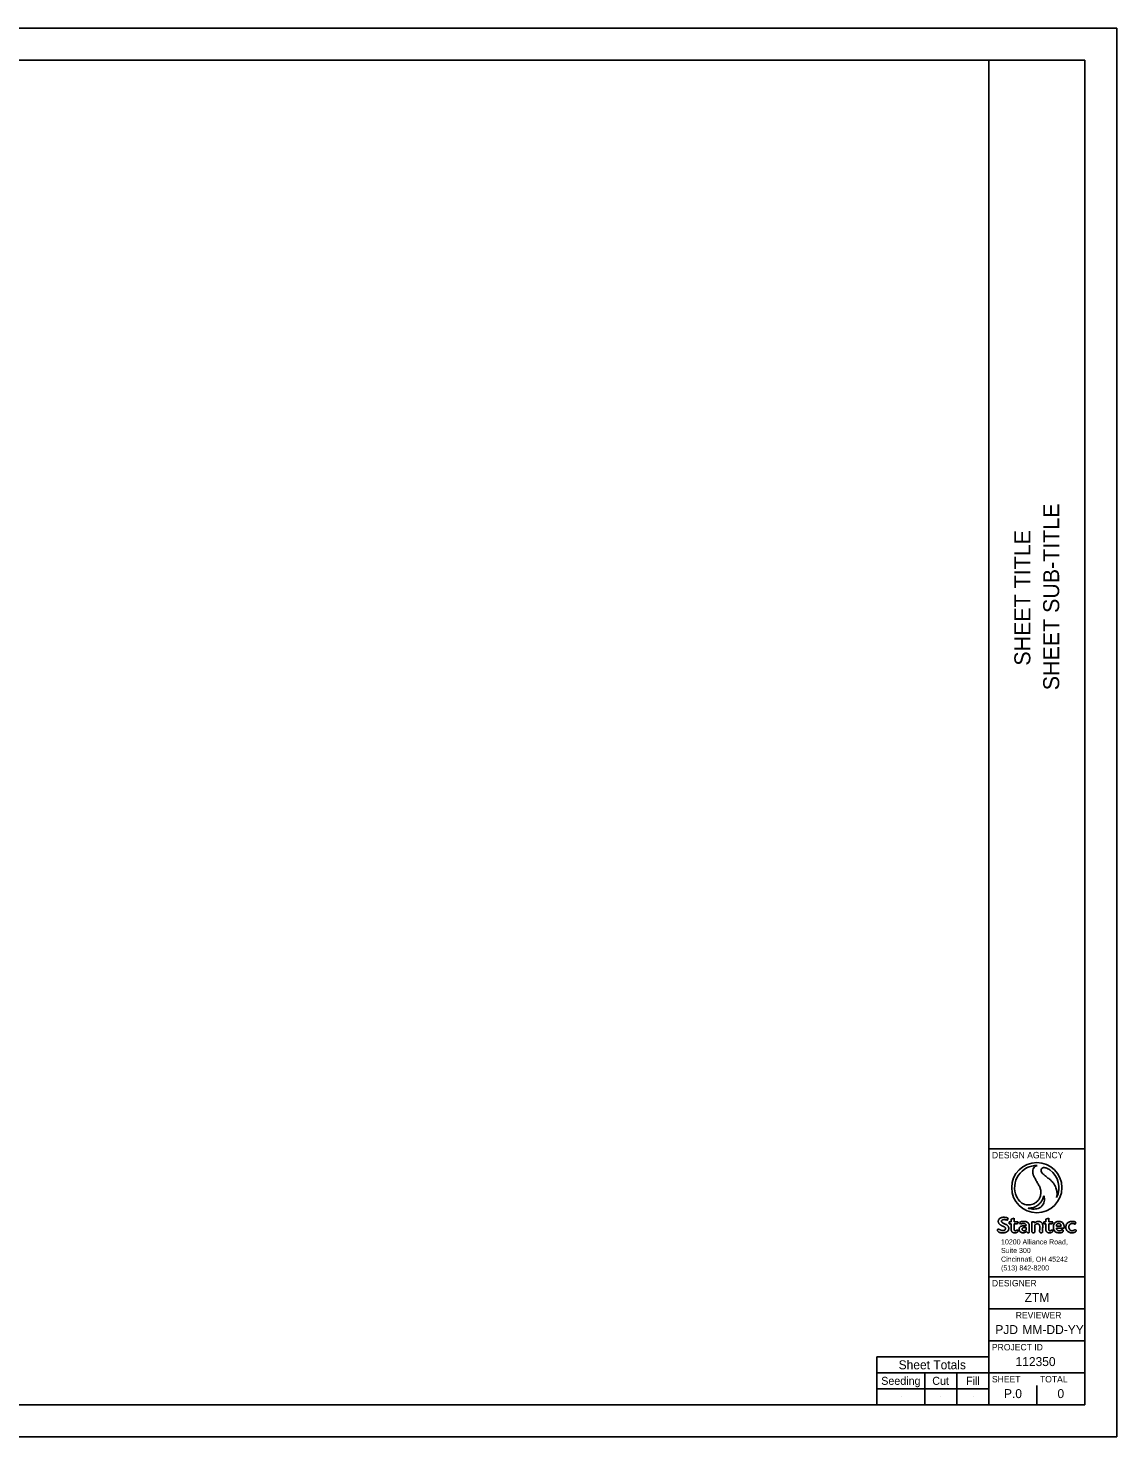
# Model space of a CAD drawing. Extents: x -31.8 to 34, y 0 to 22.
# Drawn here: x 17 to 34, y 0 to 22 of the extents above; entities that cross this region are included whole.
import ezdxf

# ---------------------------------------------------------------- set-up
doc = ezdxf.new("R2010")
doc.units = 0
for name, color, linetype in [('SH_Border', 7, 'Continuous'), ('SH_Cut_Line', 7, 'Continuous'), ('SH_Data', 7, 'Continuous'), ('SH_Text', 7, 'Continuous')]:
    doc.layers.add(name, color=color, linetype=linetype)

msp = doc.modelspace()

# ---------------------------------------------------------------- linework, layer by layer
at = {"layer": 'SH_Border'}
for p, q in [((32, 0.5), (32, 21.5)), ((32, 4.5), (33.5, 4.5)), ((32, 2.5), (33.5, 2.5)), ((32, 2), (33.5, 2)), ((32, 1.5), (33.5, 1.5)), ((32, 1), (33.5, 1))]:
    msp.add_line(p, q, dxfattribs=at)
msp.add_lwpolyline([(1.5, 21.5), (33.5, 21.5), (33.5, 0.5), (1.5, 0.5)], close=True, dxfattribs=at)
at = {"layer": 'SH_Cut_Line'}
msp.add_lwpolyline([(0, 0), (34, 0), (34, 22), (0, 22)], close=True, dxfattribs=at)
at = {"layer": 'SH_Data'}
for p, q in [((32.75, 3.5), (32.75, 3.5)), ((30.25, 0.5), (30.25, 1.25)), ((30.25, 1.25), (32, 1.25)), ((30.25, 1), (32, 1)), ((31, 0.5), (31, 1)), ((31.5, 0.5), (31.5, 1)), ((30.25, 0.75), (32, 0.75)), ((32.375, 0.675), (32.375, 0.675)), ((32.75, 0.5), (32.75, 0.8)), ((30.632, 0.625), (30.632, 0.625)), ((31.254, 0.625), (31.254, 0.625)), ((31.76, 0.625), (31.76, 0.625))]:
    msp.add_line(p, q, dxfattribs=at)
at = {"layer": 'SH_Text'}
for p, q in [((32.29, 3.381), (32.302, 3.415)), ((32.35, 3.36), (32.319, 3.36)), ((32.319, 3.36), (32.319, 3.326)), ((32.319, 3.326), (32.35, 3.326)), ((32.397, 3.413), (32.35, 3.399)), ((32.35, 3.399), (32.35, 3.36)), ((32.397, 3.36), (32.397, 3.413)), ((32.459, 3.36), (32.397, 3.36)), ((32.397, 3.242), (32.397, 3.326)), ((32.397, 3.326), (32.448, 3.326)), ((32.448, 3.326), (32.459, 3.36)), ((32.48, 3.349), (32.494, 3.32)), ((32.713, 3.36), (32.672, 3.36)), ((32.672, 3.36), (32.672, 3.207)), ((32.715, 3.34), (32.713, 3.36)), ((32.719, 3.207), (32.719, 3.308)), ((32.891, 3.36), (32.861, 3.36)), ((32.861, 3.36), (32.861, 3.326)), ((32.861, 3.326), (32.892, 3.326)), ((32.939, 3.413), (32.891, 3.399)), ((32.891, 3.399), (32.891, 3.36)), ((32.938, 3.242), (32.939, 3.326)), ((32.939, 3.36), (32.939, 3.413)), ((33.001, 3.36), (32.939, 3.36)), ((32.939, 3.326), (32.99, 3.326)), ((32.99, 3.326), (33.001, 3.36)), ((33.347, 3.319), (33.358, 3.351)), ((32.584, 3.27), (32.584, 3.232)), ((33.129, 3.289), (33.056, 3.289)), ((33.056, 3.259), (33.178, 3.259))]:
    msp.add_line(p, q, dxfattribs=at)
for points in [[(32.757, 4.238), (32.757, 4.238)], [(32.956, 4.17), (32.956, 4.17)]]:
    msp.add_lwpolyline(points, dxfattribs=at)
msp.add_circle((32.75, 3.892), 0.392, dxfattribs=at)
for start, end in [(88.7666, 203.6845), (88.7601, 88.7666), (333.7815, 53.4326), (247.1184, 251.458)]:
    msp.add_arc((32.75, 3.892), 0.346, start, end, dxfattribs=at)
for points, degree in [([(32.757, 4.238), (32.749, 4.236), (32.729, 4.232), (32.703, 4.206), (32.684, 4.163), (32.687, 4.115), (32.704, 4.068), (32.73, 4.023), (32.756, 3.973), (32.786, 3.925), (32.807, 3.877), (32.816, 3.825), (32.81, 3.773), (32.795, 3.725), (32.765, 3.681), (32.726, 3.65), (32.686, 3.632), (32.649, 3.621), (32.608, 3.621), (32.563, 3.627), (32.518, 3.648), (32.47, 3.688), (32.447, 3.728), (32.433, 3.753)], 3), ([(32.757, 4.238), (32.757, 4.238), (32.757, 4.238), (32.757, 4.238)], 2), ([(33.06, 3.74), (33.063, 3.752), (33.068, 3.774), (33.067, 3.811), (33.064, 3.843), (33.054, 3.873), (33.043, 3.907), (33.024, 3.945), (32.996, 3.98), (32.959, 4.017), (32.914, 4.05), (32.867, 4.089), (32.829, 4.117), (32.816, 4.15), (32.816, 4.175), (32.828, 4.192), (32.845, 4.204), (32.867, 4.206), (32.893, 4.201), (32.924, 4.188), (32.944, 4.177), (32.956, 4.17)], 3), ([(32.615, 3.574), (32.624, 3.573), (32.644, 3.571), (32.678, 3.578), (32.716, 3.587), (32.751, 3.607), (32.782, 3.629), (32.812, 3.661), (32.837, 3.696), (32.853, 3.733), (32.857, 3.755), (32.86, 3.766)], 3), ([(32.86, 3.766), (32.862, 3.757), (32.869, 3.735), (32.87, 3.697), (32.864, 3.656), (32.843, 3.619), (32.815, 3.585), (32.774, 3.566), (32.73, 3.557), (32.685, 3.556), (32.654, 3.562), (32.64, 3.564)], 3), ([(32.302, 3.415), (32.3, 3.416), (32.29, 3.421), (32.272, 3.426), (32.25, 3.428), (32.23, 3.429), (32.213, 3.428), (32.197, 3.424), (32.181, 3.418), (32.167, 3.408), (32.156, 3.394), (32.15, 3.38), (32.148, 3.368), (32.149, 3.356), (32.151, 3.344), (32.156, 3.335), (32.162, 3.326), (32.169, 3.319), (32.178, 3.312), (32.189, 3.305), (32.202, 3.298), (32.217, 3.291), (32.232, 3.285), (32.244, 3.279), (32.254, 3.271), (32.26, 3.264), (32.262, 3.255), (32.262, 3.246), (32.258, 3.237), (32.251, 3.229), (32.238, 3.224), (32.224, 3.222), (32.207, 3.222), (32.193, 3.225), (32.182, 3.231), (32.172, 3.235), (32.166, 3.241), (32.16, 3.243), (32.154, 3.246), (32.148, 3.245), (32.143, 3.243), (32.138, 3.239), (32.134, 3.233), (32.134, 3.226), (32.135, 3.219), (32.14, 3.212), (32.15, 3.202), (32.169, 3.193), (32.191, 3.187), (32.213, 3.186), (32.233, 3.186), (32.25, 3.189), (32.265, 3.193), (32.281, 3.2), (32.296, 3.212), (32.307, 3.227), (32.312, 3.244), (32.313, 3.259), (32.311, 3.273), (32.305, 3.285), (32.299, 3.296), (32.287, 3.305), (32.274, 3.314), (32.259, 3.321), (32.243, 3.329), (32.227, 3.336), (32.213, 3.343), (32.204, 3.352), (32.2, 3.36), (32.199, 3.369), (32.201, 3.376), (32.207, 3.383), (32.214, 3.388), (32.224, 3.392), (32.236, 3.393), (32.248, 3.392), (32.259, 3.39), (32.27, 3.388), (32.281, 3.385), (32.287, 3.383), (32.29, 3.381)], 3), ([(32.35, 3.326), (32.35, 3.296), (32.35, 3.265), (32.35, 3.23), (32.351, 3.222), (32.355, 3.21), (32.361, 3.202), (32.368, 3.196), (32.375, 3.192), (32.386, 3.188), (32.401, 3.186), (32.417, 3.187), (32.433, 3.189), (32.445, 3.195), (32.454, 3.202), (32.458, 3.21), (32.458, 3.217), (32.457, 3.224), (32.454, 3.227), (32.45, 3.229), (32.446, 3.23), (32.441, 3.23), (32.436, 3.229), (32.432, 3.226), (32.427, 3.222), (32.421, 3.219), (32.415, 3.217), (32.408, 3.218), (32.403, 3.221), (32.398, 3.226), (32.396, 3.233), (32.396, 3.239), (32.397, 3.242)], 3), ([(32.589, 3.209), (32.589, 3.207), (32.589, 3.203), (32.593, 3.197), (32.599, 3.191), (32.609, 3.186), (32.62, 3.186), (32.63, 3.188), (32.634, 3.196), (32.634, 3.204), (32.632, 3.215), (32.629, 3.244), (32.631, 3.275), (32.631, 3.309), (32.627, 3.325), (32.618, 3.34), (32.608, 3.351), (32.592, 3.359), (32.572, 3.364), (32.548, 3.366), (32.524, 3.363), (32.501, 3.358), (32.486, 3.352), (32.48, 3.349)], 3), ([(32.494, 3.32), (32.496, 3.322), (32.503, 3.325), (32.514, 3.328), (32.527, 3.332), (32.539, 3.333), (32.552, 3.332), (32.564, 3.329), (32.574, 3.323), (32.581, 3.314), (32.584, 3.306), (32.584, 3.3), (32.584, 3.298)], 3), ([(32.719, 3.308), (32.72, 3.309), (32.724, 3.312), (32.731, 3.317), (32.741, 3.323), (32.754, 3.327), (32.768, 3.327), (32.78, 3.323), (32.789, 3.314), (32.794, 3.303), (32.796, 3.289), (32.795, 3.267), (32.796, 3.239), (32.794, 3.216), (32.795, 3.201), (32.801, 3.192), (32.81, 3.186), (32.821, 3.186), (32.832, 3.189), (32.841, 3.195), (32.843, 3.208), (32.841, 3.23), (32.842, 3.257), (32.842, 3.287), (32.843, 3.307), (32.84, 3.323), (32.835, 3.335), (32.827, 3.347), (32.813, 3.356), (32.797, 3.364), (32.778, 3.365), (32.76, 3.364), (32.745, 3.358), (32.731, 3.352), (32.722, 3.345), (32.717, 3.341), (32.715, 3.34)], 3), ([(32.892, 3.326), (32.892, 3.296), (32.891, 3.265), (32.892, 3.23), (32.893, 3.222), (32.897, 3.21), (32.903, 3.202), (32.91, 3.196), (32.917, 3.192), (32.928, 3.188), (32.943, 3.186), (32.959, 3.187), (32.975, 3.189), (32.987, 3.195), (32.996, 3.202), (33, 3.21), (33, 3.217), (32.999, 3.224), (32.996, 3.227), (32.992, 3.229), (32.988, 3.23), (32.983, 3.23), (32.978, 3.229), (32.974, 3.226), (32.969, 3.222), (32.963, 3.219), (32.957, 3.217), (32.95, 3.218), (32.944, 3.221), (32.94, 3.226), (32.938, 3.233), (32.938, 3.239), (32.938, 3.242)], 3), ([(33.178, 3.259), (33.178, 3.264), (33.178, 3.276), (33.176, 3.294), (33.171, 3.315), (33.161, 3.332), (33.15, 3.346), (33.135, 3.356), (33.117, 3.363), (33.096, 3.364), (33.076, 3.364), (33.057, 3.358), (33.04, 3.348), (33.026, 3.335), (33.016, 3.318), (33.011, 3.3), (33.009, 3.282), (33.009, 3.262), (33.013, 3.243), (33.02, 3.225), (33.031, 3.21), (33.048, 3.198), (33.069, 3.187), (33.094, 3.186), (33.116, 3.186), (33.135, 3.19), (33.15, 3.197), (33.161, 3.207), (33.165, 3.217), (33.163, 3.225), (33.159, 3.232), (33.152, 3.234), (33.146, 3.235), (33.139, 3.232), (33.13, 3.227), (33.12, 3.221), (33.107, 3.218), (33.096, 3.218), (33.084, 3.221), (33.075, 3.227), (33.066, 3.235), (33.06, 3.245), (33.057, 3.253), (33.056, 3.258), (33.056, 3.259)], 3), ([(33.056, 3.289), (33.056, 3.29), (33.056, 3.294), (33.056, 3.301), (33.059, 3.31), (33.064, 3.32), (33.073, 3.328), (33.085, 3.332), (33.098, 3.332), (33.111, 3.329), (33.121, 3.322), (33.126, 3.311), (33.128, 3.299), (33.129, 3.292), (33.129, 3.289)], 3), ([(33.358, 3.351), (33.354, 3.353), (33.344, 3.359), (33.324, 3.364), (33.3, 3.366), (33.275, 3.363), (33.25, 3.355), (33.23, 3.342), (33.215, 3.323), (33.206, 3.302), (33.202, 3.278), (33.204, 3.254), (33.213, 3.232), (33.225, 3.216), (33.242, 3.201), (33.265, 3.19), (33.292, 3.186), (33.317, 3.188), (33.338, 3.193), (33.354, 3.201), (33.365, 3.211), (33.365, 3.221), (33.365, 3.228), (33.36, 3.232), (33.355, 3.235), (33.349, 3.236), (33.342, 3.235), (33.335, 3.229), (33.325, 3.225), (33.315, 3.22), (33.302, 3.219), (33.287, 3.22), (33.273, 3.228), (33.263, 3.238), (33.254, 3.251), (33.252, 3.266), (33.25, 3.281), (33.254, 3.295), (33.259, 3.309), (33.268, 3.319), (33.279, 3.327), (33.292, 3.332), (33.307, 3.333), (33.322, 3.332), (33.336, 3.327), (33.344, 3.322), (33.347, 3.319)], 3), ([(32.584, 3.298), (32.581, 3.298), (32.571, 3.298), (32.554, 3.297), (32.533, 3.296), (32.514, 3.292), (32.496, 3.285), (32.48, 3.271), (32.473, 3.252), (32.474, 3.234), (32.477, 3.219), (32.486, 3.206), (32.5, 3.194), (32.519, 3.187), (32.539, 3.187), (32.557, 3.189), (32.572, 3.194), (32.582, 3.201), (32.586, 3.206), (32.589, 3.209)], 3), ([(32.584, 3.232), (32.583, 3.231), (32.579, 3.228), (32.571, 3.224), (32.559, 3.219), (32.547, 3.218), (32.537, 3.221), (32.529, 3.226), (32.525, 3.231), (32.521, 3.238), (32.521, 3.245), (32.522, 3.252), (32.527, 3.259), (32.534, 3.264), (32.543, 3.267), (32.554, 3.269), (32.566, 3.27), (32.577, 3.27), (32.582, 3.27), (32.584, 3.27)], 3), ([(32.672, 3.207), (32.673, 3.205), (32.674, 3.201), (32.677, 3.193), (32.686, 3.186), (32.698, 3.186), (32.71, 3.187), (32.717, 3.195), (32.719, 3.202), (32.719, 3.206), (32.719, 3.207)], 3)]:
    msp.add_open_spline(points, degree=degree, dxfattribs=at)

# ---------------------------------------------------------------- texts
at = {"layer": 'SH_Data'}
for s, p in [('SHEET SUB-TITLE', (33.1, 11.66)), ('SHEET TITLE', (32.65, 12.044))]:
    msp.add_text(s, height=0.25, rotation=90, dxfattribs=at).set_placement(p)
for s, height, p in [('DESIGN AGENCY', 0.1, (32.05, 4.35)), ('DESIGNER', 0.1, (32.05, 2.35)), ('ZTM', 0.14, (32.56, 2.105)), ('REVIEWER', 0.1, (32.422, 1.85)), ('PJD', 0.14, (32.103, 1.605)), ('MM-DD-YY', 0.14, (32.527, 1.605)), ('PROJECT ID', 0.1, (32.05, 1.35)), ('Sheet Totals', 0.14, (30.593, 1.055)), ('112350', 0.14, (32.419, 1.105)), ('Seeding', 0.125, (30.321, 0.812)), ('Cut', 0.125, (31.118, 0.812)), ('Fill', 0.125, (31.646, 0.812)), ('SHEET', 0.1, (32.05, 0.85)), ('TOTAL', 0.1, (32.8, 0.85)), ('P.0', 0.14, (32.238, 0.605)), ('0', 0.14, (33.073, 0.605))]:
    msp.add_text(s, height=height, dxfattribs=at).set_placement(p)
at = {"layer": 'SH_Text'}
for s, height, p in [('10200 Alliance Road,', 0.07948, (32.192, 3.005)), ('Suite 300', 0.0795, (32.192, 2.871)), ('Cincinnati, OH 45242', 0.07948, (32.192, 2.735)), ('(513) 842-8200', 0.07948, (32.192, 2.599))]:
    msp.add_text(s, height=height, rotation=360, dxfattribs=at).set_placement(p)

doc.saveas('drawing.dxf')
